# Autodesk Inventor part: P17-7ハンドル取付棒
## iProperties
Created: 2008-07
Part Number: P17-7ハンドル取付棒
Document SubType Name: Modeling
Designer: y-shimohigashi
Density: 1 g/cm^3
Stock Number: P17-7ハンドル取付棒
Author: y-shimohigashi
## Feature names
1. 押し出し1 [Extrusion]
2. 押し出し2 [Extrusion]
3. 押し出し3 [Extrusion]
4. フィレット1 [Fillet]
5. 押し出し4 [Extrusion]
